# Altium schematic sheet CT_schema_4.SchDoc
size 411 x 401 mm
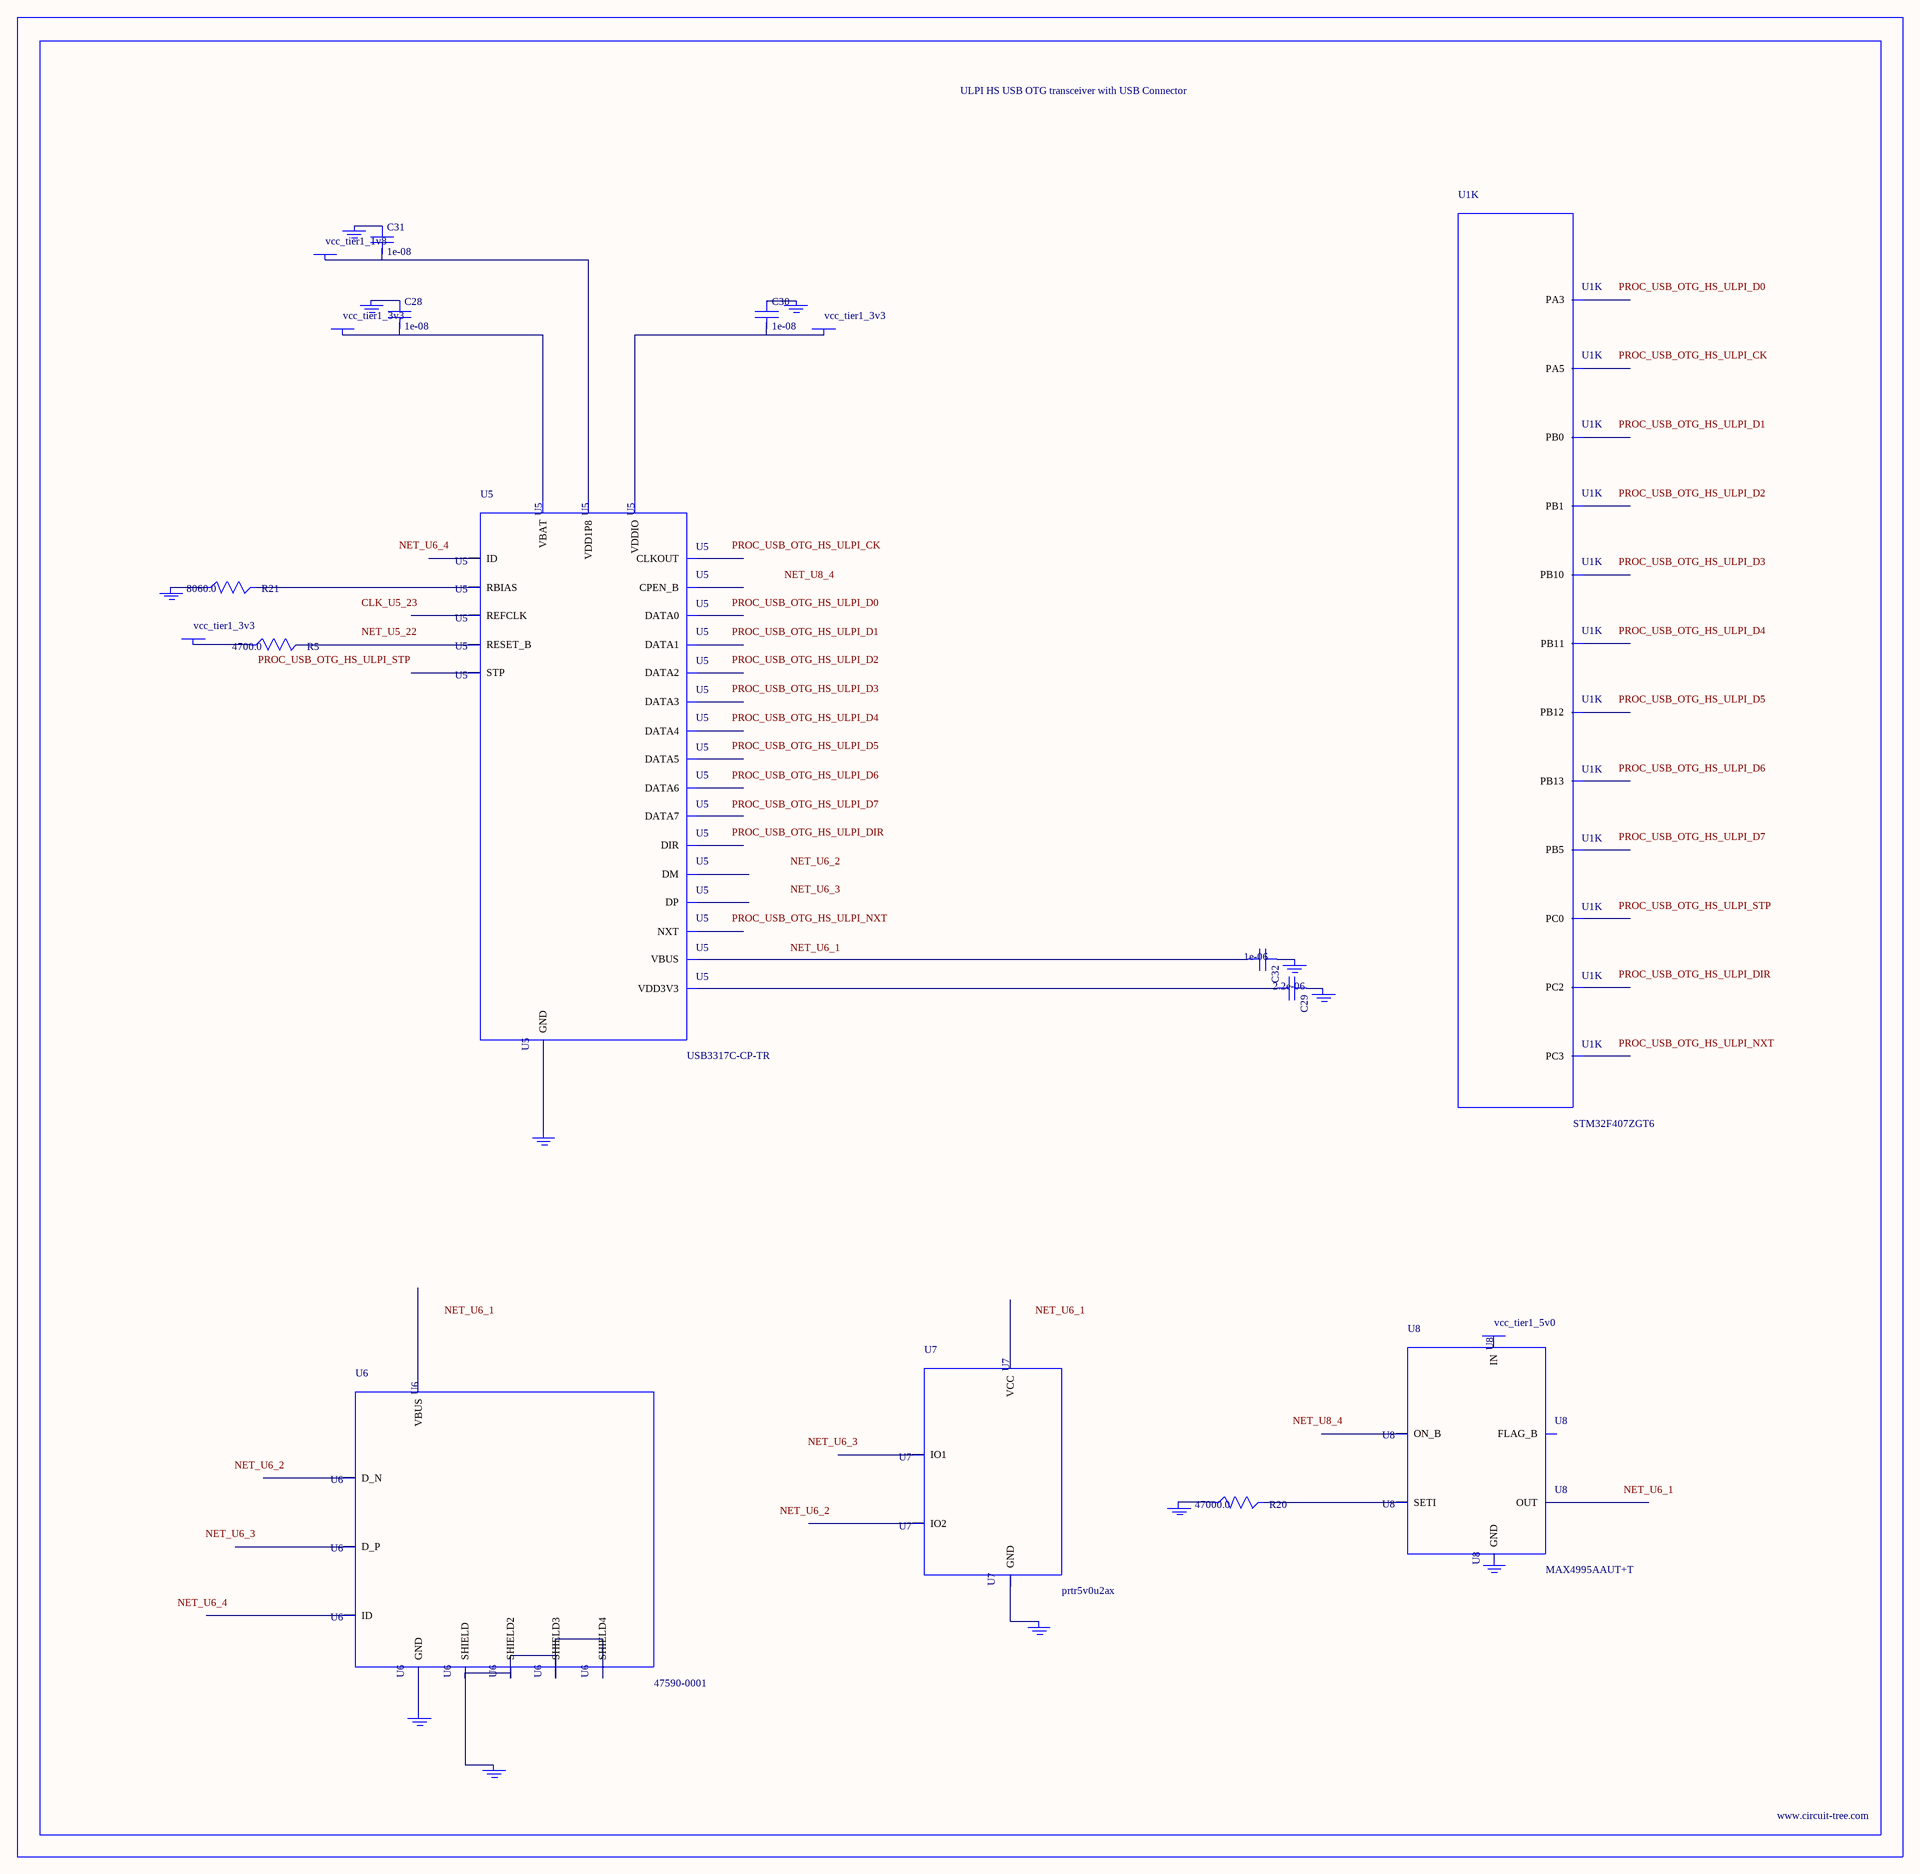
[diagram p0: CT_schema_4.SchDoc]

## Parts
BORDER3  (no value)
C28  1e-08  [C0402]
C29  2.2e-06  [C0603]
C30  1e-08  [C0402]
C31  1e-08  [C0402]
C32  1e-06  [C0603]
GND_INSTANCE_3_0  (no value)
GND_INSTANCE_3_1  (no value)
GND_INSTANCE_3_2  (no value)
GND_INSTANCE_3_3  (no value)
GND_INSTANCE_3_4  (no value)
GND_INSTANCE_3_5  (no value)
GND_INSTANCE_3_6  (no value)
GND_INSTANCE_3_7  (no value)
GND_INSTANCE_3_8  (no value)
GND_INSTANCE_3_9  (no value)
GND_INSTANCE_3_10  (no value)
GND_INSTANCE_3_11  (no value)
POWER_INSTANCE_3_0  vcc_tier1_3v3
POWER_INSTANCE_3_1  vcc_tier1_3v3
POWER_INSTANCE_3_2  vcc_tier1_1v8
POWER_INSTANCE_3_3  vcc_tier1_3v3
POWER_INSTANCE_3_4  vcc_tier1_5v0
R5  4700.0  [R0603]
R20  47000.0  [R0603]
R21  8060.0  [R0603]
U1  STM32F407ZGT6  [LQFP144]  (part K of 11)
U5  USB3317C-CP-TR  [QFN-24]
U6  47590-0001  [MICRO_USB_AB]
U7  prtr5v0u2ax  [SOT143B]
U8  MAX4995AAUT+T  [SOT-23-6]

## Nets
NetC28_1: C28.1 GND_INSTANCE_3_1.0(GND)
NetC28_2: C28.2 POWER_INSTANCE_3_0.0(PWR) U5.3(VBAT)
NetC29_1: C29.1 GND_INSTANCE_3_2.0(GND)
NetC29_2: C29.2 U5.4(VDD3V3)
NetC30_1: C30.1 GND_INSTANCE_3_3.0(GND)
NetC30_2: C30.2 POWER_INSTANCE_3_1.0(PWR) U5.17(VDDIO)
NetC31_1: C31.1 GND_INSTANCE_3_4.0(GND)
NetC31_2: C31.2 POWER_INSTANCE_3_2.0(PWR) U5.21(VDD1P8)
NetC32_1: C32.1 GND_INSTANCE_3_0.0(GND)
NetC32_2: C32.2 U5.2(VBUS)
NetGND_INSTANCE_3_5_0: GND_INSTANCE_3_5.0(GND) R21.1
NetGND_INSTANCE_3_6_0: GND_INSTANCE_3_6.0(GND) U5.25(GND)
NetGND_INSTANCE_3_7_0: GND_INSTANCE_3_7.0(GND) U6.6(SHIELD) U6.7(SHIELD2) U6.8(SHIELD3) U6.9(SHIELD4)
NetGND_INSTANCE_3_8_0: GND_INSTANCE_3_8.0(GND) U6.5(GND)
NetGND_INSTANCE_3_9_0: GND_INSTANCE_3_9.0(GND) U7.1(GND)
NetGND_INSTANCE_3_10_0: GND_INSTANCE_3_10.0(GND) R20.1
NetPOWER_INSTANCE_3_3_0: POWER_INSTANCE_3_3.0(PWR) R5.1
NetR5_2: R5.2 U5.22(RESET_B)
NetR20_2: R20.2 U8.3(SETI)
NetR21_2: R21.2 U5.24(RBIAS)

Not connected (* = marked no-connect by the designer): GND_INSTANCE_3_11 0(GND); POWER_INSTANCE_3_4 0(PWR); U1 26(PC0) 28(PC2) 29(PC3) 37(PA3) 41(PA5) 46(PB0) 47(PB1) 69(PB10) 70(PB11) 73(PB12) 74(PB13) 135(PB5); U5 1(ID) 5(DM) 6(DP) 7(CPEN_B) 8(DATA7) 9(DATA6) 10(DATA5) 11(DATA4) 12(CLKOUT) 13(DATA3) 14(DATA2) 15(DATA1) 16(DATA0) 18(NXT) 19(DIR) 20(STP) 23(REFCLK); U6 1(VBUS) 2(D_N) 3(D_P) 4(ID); U7 2(IO1) 3(IO2) 4(VCC); U8 1(OUT) 2(GND) 4(ON_B) 5(IN) 6(FLAG_B)

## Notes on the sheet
- Labels drawn without touching a wire or pin: CLK_U5_23, NET_U5_22, NET_U6_1, NET_U6_2, NET_U6_3, NET_U6_4, NET_U8_4, PROC_USB_OTG_HS_ULPI_CK, PROC_USB_OTG_HS_ULPI_D0, PROC_USB_OTG_HS_ULPI_D1, PROC_USB_OTG_HS_ULPI_D2, PROC_USB_OTG_HS_ULPI_D3, PROC_USB_OTG_HS_ULPI_D4, PROC_USB_OTG_HS_ULPI_D5, PROC_USB_OTG_HS_ULPI_D6, PROC_USB_OTG_HS_ULPI_D7, PROC_USB_OTG_HS_ULPI_DIR, PROC_USB_OTG_HS_ULPI_NXT, PROC_USB_OTG_HS_ULPI_STP

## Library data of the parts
BORDER3 = BORDER_PAGE3
C28 C30 C31 = C0402C103K3RAC
C29 = C0603C225K8RACTU
C32 = C0603C105K3RACTU
GND_INSTANCE_3_0-GND_INSTANCE_3_11 = GND
POWER_INSTANCE_3_0-POWER_INSTANCE_3_4 = PWR
R5 = RC0603JR-074K7L
R20 = RC0603JR-0747KL
R21 = ERJ-3EKF8061V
